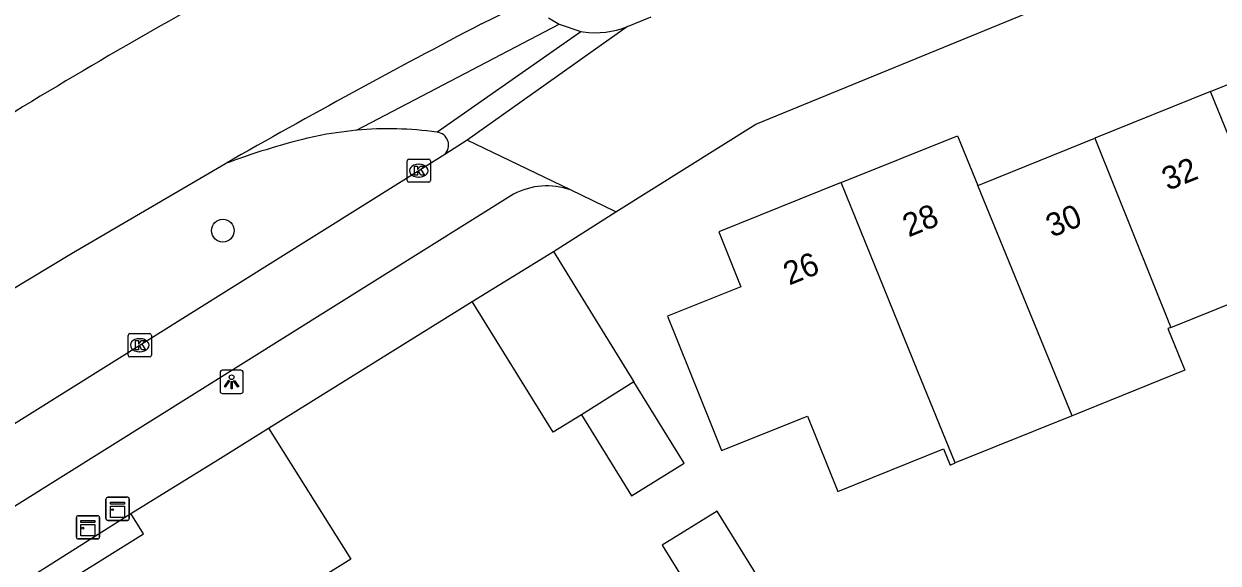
# Model space of a CAD drawing. Extents: x 157767 to 159171, y 387842 to 389425.
# Drawn here: x 158354.9 to 158406.4, y 388283.9 to 388307.1 of the extents above; entities that cross this region are included whole.
import ezdxf

# ---------------------------------------------------------------- set-up
doc = ezdxf.new("R2010")
doc.units = 0
for name, color, linetype in [('IMGEO_Boom', 7, 'Continuous'), ('IMGEO_Fietspad_open', 7, 'Continuous'), ('IMGEO_Kast', 7, 'Continuous'), ('IMGEO_Kolk', 7, 'Continuous'), ('IMGEO_Lichtpunt', 7, 'Continuous'), ('IMGEO_Muur', 7, 'Continuous'), ('IMGEO_Pand', 7, 'Continuous'), ('IMGEO_Pand_nummerreeks', 7, 'Continuous'), ('IMGEO_Rijbaan_lokaal_gesloten', 7, 'Continuous'), ('IMGEO_Rijbaan_lokaal_open', 7, 'Continuous'), ('IMGEO_Voetpad_open', 7, 'Continuous')]:
    doc.layers.add(name, color=color, linetype=linetype)

msp = doc.modelspace()

# ---------------------------------------------------------------- linework, layer by layer
at = {"layer": 'IMGEO_Boom'}
msp.add_circle((158363.505, 388298.176), 0.489, dxfattribs=at)
at = {"layer": 'IMGEO_Fietspad_open'}
for points in [[(158374.028, 388302.069), (158373.056, 388301.46)], [(158373.056, 388301.46), (158353.052, 388288.935)], [(158376.024, 388299.744), (158350.757, 388283.935)]]:
    msp.add_lwpolyline(points, dxfattribs=at)
msp.add_arc((158377.455, 388297.089), 3.016, 70.2593, 118.3306, dxfattribs=at)
at = {"layer": 'IMGEO_Kast'}
for p, q in [((158358.475, 388285.769), (158358.475, 388286.61)), ((158358.475, 388286.61), (158358.475, 388285.769)), ((158358.55, 388286.694), (158359.391, 388286.694)), ((158359.391, 388286.694), (158358.55, 388286.694)), ((158359.475, 388286.619), (158359.475, 388285.778)), ((158359.475, 388285.778), (158359.475, 388286.619)), ((158357.274, 388285.896), (158358.115, 388285.896)), ((158358.115, 388285.896), (158357.274, 388285.896)), ((158357.199, 388284.971), (158357.199, 388285.812)), ((158357.199, 388285.812), (158357.199, 388284.971)), ((158358.199, 388285.821), (158358.199, 388284.98)), ((158358.199, 388284.98), (158358.199, 388285.821)), ((158359.4, 388285.694), (158358.559, 388285.694)), ((158358.559, 388285.694), (158359.4, 388285.694)), ((158358.124, 388284.896), (158357.283, 388284.896)), ((158357.283, 388284.896), (158358.124, 388284.896))]:
    msp.add_line(p, q, dxfattribs=at)
for points in [[(158358.67, 388286.484), (158359.27, 388286.484), (158359.27, 388286.399), (158358.67, 388286.399), (158358.67, 388286.484)], [(158358.67, 388286.309), (158359.27, 388286.309), (158359.27, 388285.82), (158358.67, 388285.82), (158358.67, 388286.309)], [(158357.394, 388285.686), (158357.994, 388285.686), (158357.994, 388285.601), (158357.394, 388285.601), (158357.394, 388285.686)], [(158357.394, 388285.511), (158357.994, 388285.511), (158357.994, 388285.022), (158357.394, 388285.022), (158357.394, 388285.511)]]:
    msp.add_lwpolyline(points, dxfattribs=at)
for centre in [(158358.754, 388286.158), (158357.478, 388285.36)]:
    msp.add_circle(centre, 0.0377, dxfattribs=at)
for centre, start, end in [((158358.553, 388286.616), 92.4484, 184.2845), ((158358.553, 388286.616), 92.4484, 184.2845), ((158359.397, 388286.616), 2.4484, 94.2845), ((158359.397, 388286.616), 2.4484, 94.2845), ((158357.277, 388285.818), 92.4484, 184.2845), ((158357.277, 388285.818), 92.4484, 184.2845), ((158358.121, 388285.818), 2.4484, 94.2845), ((158358.121, 388285.818), 2.4484, 94.2845), ((158358.553, 388285.772), 182.4484, 274.2845), ((158358.553, 388285.772), 182.4484, 274.2845), ((158359.397, 388285.772), 272.4484, 4.2845), ((158359.397, 388285.772), 272.4484, 4.2845), ((158357.277, 388284.974), 182.4484, 274.2845), ((158357.277, 388284.974), 182.4484, 274.2845), ((158358.121, 388284.974), 272.4484, 4.2845), ((158358.121, 388284.974), 272.4484, 4.2845)]:
    msp.add_arc(centre, 0.0779, start, end, dxfattribs=at)
at = {"layer": 'IMGEO_Kolk'}
for p, q in [((158371.44, 388300.335), (158371.44, 388301.187)), ((158371.515, 388301.261), (158372.367, 388301.261)), ((158371.928, 388301.041), (158371.953, 388301.041)), ((158372.441, 388301.187), (158372.441, 388300.335)), ((158372.367, 388300.261), (158371.515, 388300.261)), ((158371.951, 388300.481), (158371.926, 388300.481)), ((158359.427, 388292.813), (158359.427, 388293.665)), ((158359.502, 388293.739), (158360.354, 388293.739)), ((158360.428, 388293.665), (158360.428, 388292.813)), ((158359.915, 388293.519), (158359.94, 388293.519)), ((158360.354, 388292.739), (158359.502, 388292.739)), ((158359.938, 388292.959), (158359.913, 388292.959))]:
    msp.add_line(p, q, dxfattribs=at)
for points in [[(158371.44, 388300.335), (158371.44, 388301.187)], [(158371.515, 388301.261), (158372.367, 388301.261)], [(158371.761, 388300.961), (158371.884, 388300.961), (158371.884, 388300.81), (158372.014, 388300.961), (158372.178, 388300.961), (158372.032, 388300.81), (158372.185, 388300.561), (158372.033, 388300.561), (158371.948, 388300.725), (158371.884, 388300.658), (158371.884, 388300.561), (158371.761, 388300.561), (158371.761, 388300.961)], [(158372.441, 388301.187), (158372.441, 388300.335)], [(158372.367, 388300.261), (158371.515, 388300.261)], [(158359.427, 388292.813), (158359.427, 388293.665)], [(158359.502, 388293.739), (158360.354, 388293.739)], [(158360.428, 388293.665), (158360.428, 388292.813)], [(158359.748, 388293.439), (158359.871, 388293.439), (158359.871, 388293.288), (158360.001, 388293.439), (158360.165, 388293.439), (158360.019, 388293.288), (158360.172, 388293.039), (158360.02, 388293.039), (158359.935, 388293.203), (158359.871, 388293.136), (158359.871, 388293.039), (158359.748, 388293.039), (158359.748, 388293.439)], [(158360.354, 388292.739), (158359.502, 388292.739)]]:
    msp.add_lwpolyline(points, dxfattribs=at)
for centre, start, end in [((158371.517, 388301.185), 91.552, 178.448), ((158371.517, 388301.185), 91.552, 178.448), ((158372.365, 388301.185), 1.552, 88.448), ((158372.365, 388301.185), 1.552, 88.448), ((158371.517, 388300.337), 181.552, 268.448), ((158371.517, 388300.337), 181.552, 268.448), ((158372.365, 388300.337), 271.552, 358.448), ((158372.365, 388300.337), 271.552, 358.448), ((158359.504, 388293.663), 91.552, 178.448), ((158359.504, 388293.663), 91.552, 178.448), ((158360.352, 388293.663), 1.552, 88.448), ((158360.352, 388293.663), 1.552, 88.448), ((158359.504, 388292.815), 181.552, 268.448), ((158359.504, 388292.815), 181.552, 268.448), ((158360.352, 388292.815), 271.552, 358.448), ((158360.352, 388292.815), 271.552, 358.448)]:
    msp.add_arc(centre, 0.0765, start, end, dxfattribs=at)
for centre, major_axis, ratio, start_param, end_param in [((158371.927, 388300.761), (-0.387, 0.002), 0.722429, 4.712389, 7.853982), ((158371.952, 388300.761), (-0.39, 0.002), 0.717154, 1.570796, 4.712389), ((158359.914, 388293.239), (-0.387, 0.002), 0.722429, 4.712389, 7.853982), ((158359.939, 388293.239), (-0.39, 0.002), 0.717154, 1.570796, 4.712389)]:
    msp.add_ellipse(centre, major_axis=major_axis, ratio=ratio, start_param=start_param, end_param=end_param, dxfattribs=at)
at = {"layer": 'IMGEO_Lichtpunt'}
for p, q in [((158363.385, 388292.064), (158363.385, 388291.257)), ((158363.385, 388292.064), (158363.385, 388291.257)), ((158364.287, 388292.159), (158363.479, 388292.159)), ((158364.287, 388292.159), (158363.479, 388292.159)), ((158364.381, 388291.257), (158364.381, 388292.064)), ((158364.381, 388291.257), (158364.381, 388292.064)), ((158363.479, 388291.163), (158364.287, 388291.163)), ((158363.479, 388291.163), (158364.287, 388291.163))]:
    msp.add_line(p, q, dxfattribs=at)
for points in [[(158363.759, 388291.728), (158363.798, 388291.7), (158363.61, 388291.438), (158363.572, 388291.465), (158363.759, 388291.728)], [(158363.861, 388291.68), (158363.908, 388291.68), (158363.908, 388291.358), (158363.861, 388291.358), (158363.861, 388291.68)], [(158363.971, 388291.7), (158364.009, 388291.727), (158364.196, 388291.465), (158364.157, 388291.437), (158363.971, 388291.7)]]:
    msp.add_lwpolyline(points, dxfattribs=at)
msp.add_circle((158363.884, 388291.862), 0.0994, dxfattribs=at)
for centre, start, end in [((158363.479, 388292.064), 90, 180), ((158363.479, 388292.064), 90, 180), ((158364.287, 388292.064), 0, 90), ((158364.287, 388292.064), 0, 90), ((158363.479, 388291.257), 180, 270), ((158363.479, 388291.257), 180, 270), ((158364.287, 388291.257), 270, 0), ((158364.287, 388291.257), 270, 360)]:
    msp.add_arc(centre, 0.0946, start, end, dxfattribs=at)
at = {"layer": 'IMGEO_Muur'}
msp.add_lwpolyline([(158365.475, 388289.674), (158374.241, 388295.13)], dxfattribs=at)
at = {"layer": 'IMGEO_Pand'}
for points in [[(158406.031, 388304.164), (158411.037, 388306.184)], [(158406.031, 388304.164), (158401.05, 388302.155)], [(158409.346, 388296.035), (158406.031, 388304.164)], [(158390.124, 388300.246), (158395.131, 388302.266), (158396.008, 388300.121)], [(158396.008, 388300.121), (158396.231, 388300.211), (158401.05, 388302.155)], [(158401.05, 388302.155), (158404.321, 388294.007)], [(158390.124, 388300.246), (158384.858, 388298.122), (158385.81, 388295.762), (158382.646, 388294.486), (158384.516, 388289.85), (158384.98, 388288.7), (158388.671, 388290.189), (158389.985, 388286.935), (158394.538, 388288.773), (158394.819, 388288.078), (158395.04, 388288.167)], [(158395.04, 388288.167), (158393.43, 388292.11), (158390.124, 388300.246)], [(158400.067, 388290.2), (158396.008, 388300.121)], [(158374.241, 388295.13), (158377.739, 388297.275)], [(158377.739, 388297.275), (158379.006, 388295.224), (158381.202, 388291.668)], [(158404.321, 388294.007), (158409.346, 388296.035)], [(158378.945, 388290.243), (158377.725, 388289.49), (158374.241, 388295.13)], [(158404.321, 388294.007), (158404.189, 388293.954), (158404.915, 388292.16), (158400.067, 388290.2)], [(158381.202, 388291.668), (158378.945, 388290.243)], [(158378.945, 388290.243), (158381.102, 388286.751), (158383.373, 388288.154), (158381.202, 388291.668)], [(158400.067, 388290.2), (158395.04, 388288.167)], [(158359.546, 388285.985), (158363.283, 388288.308), (158365.475, 388289.674)], [(158365.475, 388289.674), (158369.013, 388284.029), (158366.804, 388282.645), (158363.185, 388280.377)], [(158355.717, 388275.697), (158352.715, 388280.513), (158360.09, 388285.11), (158359.546, 388285.985)], [(158386.977, 388282.545), (158384.783, 388286.087), (158382.42, 388284.624), (158384.615, 388281.081)]]:
    msp.add_lwpolyline(points, dxfattribs=at)
at = {"layer": 'IMGEO_Rijbaan_lokaal_gesloten'}
for points in [[(158374.642, 388307.084), (158377.408, 388308.456)], [(158350.21, 388293.055), (158351.701, 388294), (158356.997, 388297.192), (158363.613, 388301.064)]]:
    msp.add_lwpolyline(points, dxfattribs=at)
for centre, radius, start, end in [((158445.272, 388152.814), 181.277, 117.72911, 121.91936), ((158462.626, 388127.262), 206.562, 118.21969, 122.02368), ((158532.3, 388005.133), 340.632, 117.5704, 119.684)]:
    msp.add_arc(centre, radius, start, end, dxfattribs=at)
at = {"layer": 'IMGEO_Rijbaan_lokaal_open'}
for points in [[(158380.421, 388298.991), (158386.453, 388302.761), (158424.712, 388318.46)], [(158380.927, 388306.975), (158374.028, 388302.069)], [(158380.927, 388306.975), (158381.944, 388307.393)], [(158378.474, 388299.928), (158374.028, 388302.069)], [(158380.421, 388298.991), (158378.474, 388299.928)]]:
    msp.add_lwpolyline(points, dxfattribs=at)
at = {"layer": 'IMGEO_Voetpad_open'}
for points in [[(158369.258, 388302.501), (158377.986, 388307.068)], [(158377.52, 388307.345), (158377.986, 388307.068)], [(158377.986, 388307.068), (158378.916, 388306.759)], [(158372.72, 388302.422), (158378.916, 388306.759)], [(158378.916, 388306.759), (158379.025, 388306.741)], [(158369.258, 388302.501), (158367.97, 388302.328), (158367.153, 388302.159)], [(158377.739, 388297.275), (158380.421, 388298.991)], [(158365.475, 388289.674), (158374.241, 388295.13)], [(158350.431, 388278.511), (158351.997, 388281.225), (158359.546, 388285.985)]]:
    msp.add_lwpolyline(points, dxfattribs=at)
for centre, radius, start, end in [((158379.559, 388310.245), 3.544, 261.3292, 292.6983), ((158370.643, 388287.3), 15.264, 82.1795, 95.2061), ((158372.664, 388301.862), 0.562, 17.8767, 84.2515), ((158374.95, 388270.684), 32.427, 103.9125, 110.4634), ((158372.668, 388301.862), 0.559, 314.0133, 18.055)]:
    msp.add_arc(centre, radius, start, end, dxfattribs=at)

# ---------------------------------------------------------------- texts
at = {"layer": 'IMGEO_Pand_nummerreeks'}
for s, rotation, p in [('32', 21.9691, (158404.189, 388299.884)), ('28', 21.9672, (158393.027, 388297.881)), ('30', 21.9672, (158399.195, 388297.87)), ('26', 21.9686, (158387.887, 388295.807))]:
    msp.add_text(s, height=1, rotation=rotation, dxfattribs=at).set_placement(p)

doc.saveas('drawing.dxf')
